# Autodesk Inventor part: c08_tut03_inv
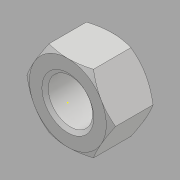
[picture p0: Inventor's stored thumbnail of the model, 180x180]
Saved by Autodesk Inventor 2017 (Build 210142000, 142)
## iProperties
Created: 2016-05
Part Number: c08_tut03_inv
Material: Generic
Document SubType Name: Modeling
Designer: CADCIM
Density: 1 g/cm^3
Appearance: Default
Author: CADCIM
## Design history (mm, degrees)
sketch "Sketch1"
  geometry: L1 (-10, 0)-(-5, 8.66); L2 (-5, 8.66)-(5, 8.66); L3 (5, 8.66)-(10, 0); L4 (10, 0)-(5, -8.66); L5 (5, -8.66)-(-5, -8.66); L6 (-5, -8.66)-(-10, 0); 2 further points
  constraints: 12 end point, 1 coincident, 13 other
  dimensions: "d6" = 20 distance of L3.end L1.start
extrude "Extrusion1" new body sketch "Sketch1" distance "d0" = 10; taper "d1" = 0 deg
sketch "Sketch2"
  geometry: L1 (10, 0)-(5, 8.66) reference; C1 r 8.66 at (0, 0); 1 further point
  constraints: 1 centre point, 1 coincident, 1 tangent
extrude "Extrusion2" sketch "Sketch2" distance "d2" = 10; taper "d3" = 60 deg
workplane "Work Plane1"
sketch "Sketch3"
  geometry: L1 (10, 0)-(5, 8.66) reference; C1 r 8.66 at (0, 0); 1 further point
  constraints: 1 centre point, 1 coincident, 1 tangent
extrude "Extrusion3" sketch "Sketch3" distance "d4" = 10; taper "d5" = 60 deg
sketch "Sketch4"
  geometry: 1 further point
hole "Hole1" diameter "d9" = 10; stored, may be unused: countersink angle "d13" = 90 deg, drill point angle "d15" = 118 deg; dims "d7" = 10, "d8" = 10, "d10" = 20, "d11" = 4, "d12" = 2, "d14" = 27.3
thread "Thread1" dims "d16" = 10, "d17" = 0
sketch "Sketch7"
  geometry: L1 (5.845, 10)-(5, 10); L2 (5, 10)-(5, 9.408); L3 (5, 9.408)-(5.845, 10); L4 (0, 0)-(0, 15.432); L5 (-5, 10)-(5, 10) reference
  constraints: 8 end point, 1 horizontal, 1 perpendicular, 1 point on line, 1 vertical
  dimensions: "d20" = 35 deg angle of L3 L1; "d21" = 0.845 distance of L1.start L1.end; "d22" = 10 vertical distance of L1.end L4
revolve "Revolution1" sketch "Sketch7" stored, may be unused: angle "d23" = 90 deg
workplane "Work Plane2"
mirror "Mirror1"
body "Solid1"
